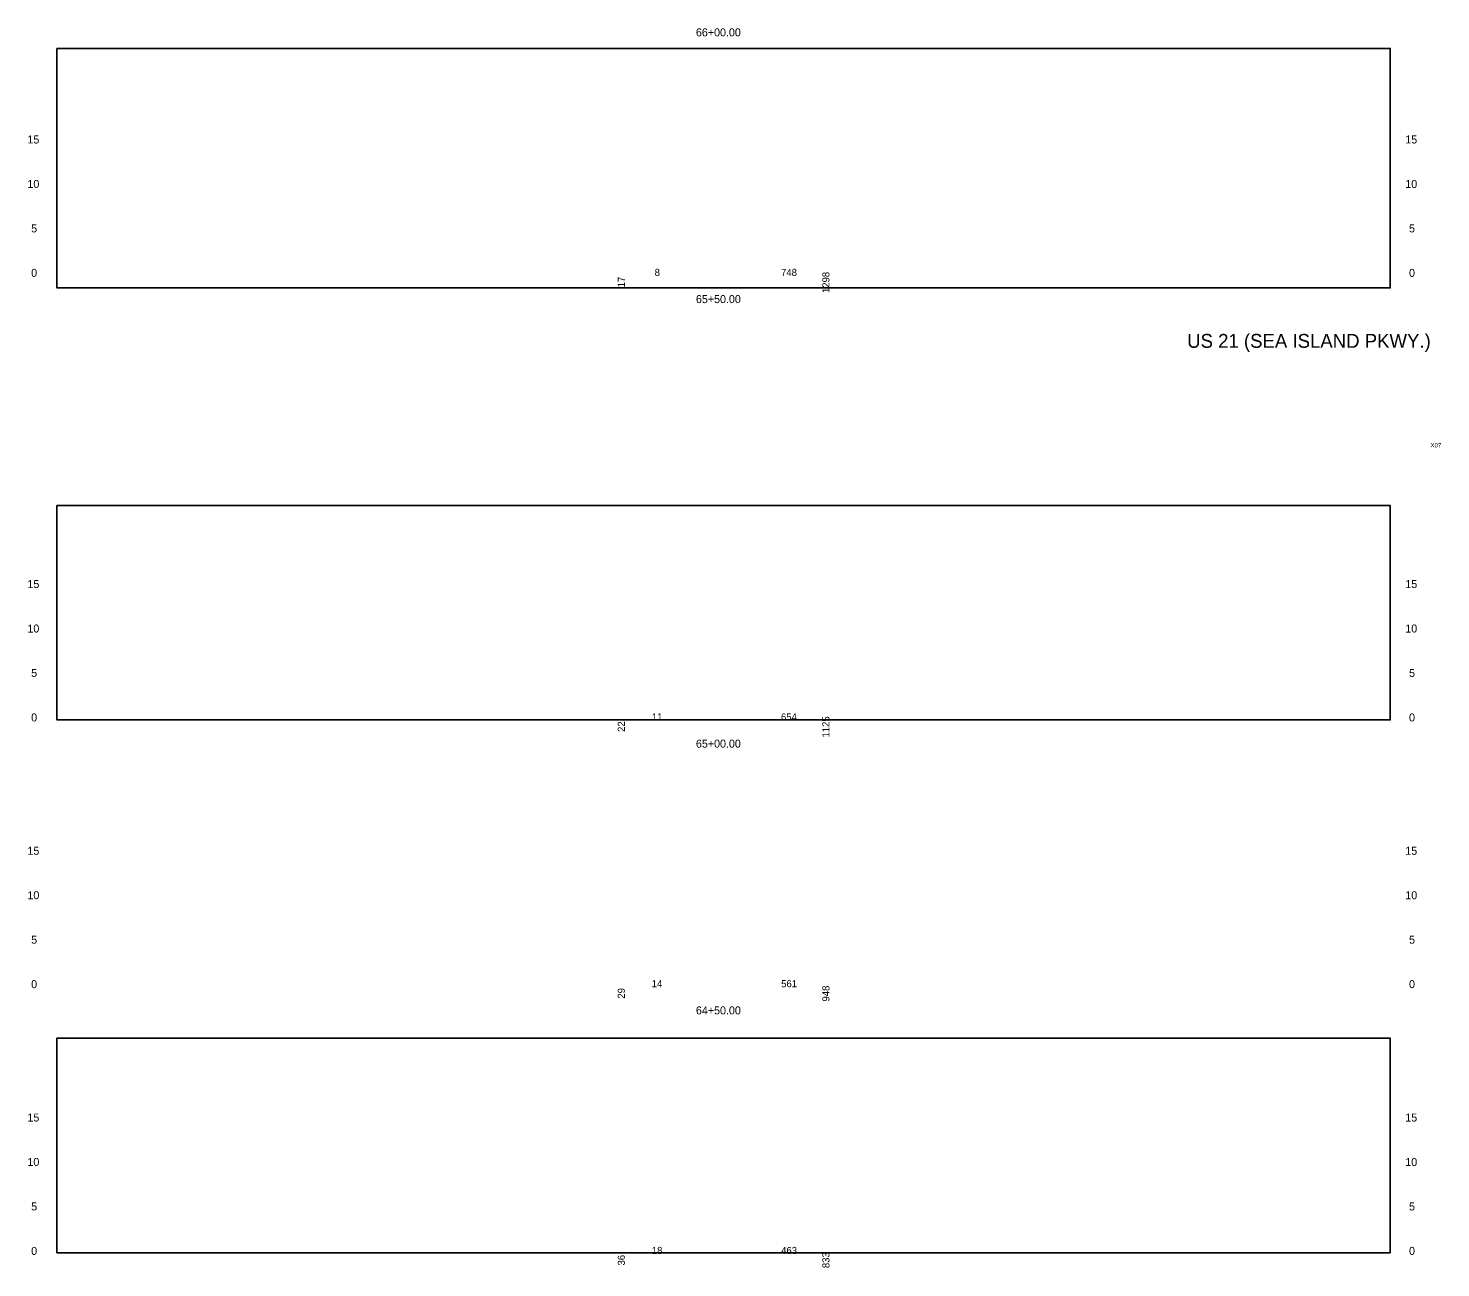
# Model space of a CAD drawing. Extents: x 971 to 1131, y 2203 to 6043.
# Drawn here: x 971.5 to 1130.4, y 2870.4 to 3009.8 of the extents above; entities that cross this region are included whole.
import ezdxf

# ---------------------------------------------------------------- set-up
doc = ezdxf.new("R2010")
doc.units = 0
for name, color, linetype in [('RD_SHT_Misc1', 7, 'Continuous'), ('RD_SHT_ShtClip', 7, 'Continuous'), ('RD_SHT_TX', 7, 'Continuous'), ('RD_XS_TX_Station', 7, 'Continuous')]:
    doc.layers.add(name, color=color, linetype=linetype)

msp = doc.modelspace()

# ---------------------------------------------------------------- linework, layer by layer
at = {"layer": 'RD_SHT_ShtClip'}
for points in [[(974.73, 3007.57), (1124.73, 3007.57), (1124.73, 2980.63), (974.73, 2980.63)], [(974.73, 2956.15), (1124.73, 2956.15), (1124.73, 2932.04), (974.73, 2932.04)], [(974.73, 2896.23), (1124.73, 2896.23), (1124.73, 2872.12), (974.73, 2872.12)]]:
    msp.add_lwpolyline(points, close=True, dxfattribs=at)

# ---------------------------------------------------------------- texts
at = {"layer": 'RD_SHT_Misc1'}
for s, p in [('8', (1041.98, 2981.97)), ('748', (1056.2, 2981.97)), ('11', (1041.66, 2931.97)), ('654', (1056.19, 2931.97)), ('14', (1041.65, 2901.97)), ('561', (1056.21, 2901.97)), ('18', (1041.66, 2871.97)), ('463', (1056.21, 2871.97))]:
    msp.add_text(s, height=0.8, dxfattribs=at).set_placement(p)
for s, p in [('17', (1038.63, 2980.69)), ('1298', (1061.64, 2980.05)), ('22', (1038.63, 2930.69)), ('1125', (1061.64, 2930.06)), ('29', (1038.63, 2900.69)), ('948', (1061.64, 2900.37)), ('36', (1038.63, 2870.68)), ('833', (1061.64, 2870.38))]:
    msp.add_text(s, height=0.8, rotation=90, dxfattribs=at).set_placement(p)
at = {"layer": 'RD_SHT_TX'}
for s, height, p in [('15', 0.9, (971.42, 2996.87)), ('15', 0.9, (1126.42, 2996.87)), ('10', 0.9, (971.42, 2991.87)), ('10', 0.9, (1126.42, 2991.87)), ('5', 0.9, (971.84, 2986.87)), ('5', 0.9, (1126.84, 2986.87)), ('0', 0.9, (971.84, 2981.87)), ('0', 0.9, (1126.84, 2981.87)), ('US 21 (SEA ISLAND PKWY.)', 1.5625, (1101.88, 2973.89)), ('15', 0.9, (971.42, 2946.87)), ('15', 0.9, (1126.42, 2946.87)), ('10', 0.9, (971.42, 2941.87)), ('10', 0.9, (1126.42, 2941.87)), ('5', 0.9, (971.84, 2936.87)), ('5', 0.9, (1126.84, 2936.87)), ('0', 0.9, (971.84, 2931.87)), ('0', 0.9, (1126.84, 2931.87)), ('15', 0.9, (971.42, 2916.87)), ('15', 0.9, (1126.42, 2916.87)), ('10', 0.9, (971.42, 2911.87)), ('10', 0.9, (1126.42, 2911.87)), ('5', 0.9, (971.84, 2906.87)), ('5', 0.9, (1126.84, 2906.87)), ('0', 0.9, (971.84, 2901.87)), ('0', 0.9, (1126.84, 2901.87)), ('15', 0.9, (971.42, 2886.87)), ('15', 0.9, (1126.42, 2886.87)), ('10', 0.9, (971.42, 2881.87)), ('10', 0.9, (1126.42, 2881.87)), ('5', 0.9, (971.84, 2876.87)), ('5', 0.9, (1126.84, 2876.87)), ('0', 0.9, (971.84, 2871.87)), ('0', 0.9, (1126.84, 2871.87))]:
    msp.add_text(s, height=height, dxfattribs=at).set_placement(p)
msp.add_text('X07', height=0.5, rotation=360, dxfattribs=at).set_placement((1129.25, 2962.68))
at = {"layer": 'RD_XS_TX_Station'}
for s, p in [('66+00.00', (1046.62, 3008.92)), ('65+50.00', (1046.62, 2978.92)), ('65+00.00', (1046.62, 2928.92)), ('64+50.00', (1046.62, 2898.92))]:
    msp.add_text(s, height=0.9, dxfattribs=at).set_placement(p)

doc.saveas('drawing.dxf')
